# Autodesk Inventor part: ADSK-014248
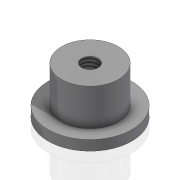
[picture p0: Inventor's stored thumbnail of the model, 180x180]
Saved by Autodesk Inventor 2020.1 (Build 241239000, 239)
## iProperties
Created: 2019-10
Part Number: ADSK-014248
Material: 1.0501 C35
Document SubType Name: Modeling
Designer: lutzd
Mass: 27.3113 g
Surface Area: 20.2779 cm^2
Volume: 3.48359 cm^3
Density: 7.84 g/cm^3
Appearance: Stahl
VLDS_Profile: Default Part
VLDS_TimeStamp: 2016-07-29
VLDS_FailCnt: 0
VLDS_AcceptCnt: 0
Dimensions: 25x25x14 mm
Mass: 0,027 kg
DocNumber: ADSK-014248
Folder: 01 - Themengebiete\Simplification\01 - Packaging machine\
VDS_Category: 3D Komponenten
VDS_NumSchm: Autodesk
Title: shaft
Author: lutzd
Revision Number: -
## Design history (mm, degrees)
sketch "Skizze1"
  geometry: C1 r 8.5 at (0, 0); 1 further point
  constraints: 1 centre point, 1 coincident
  dimensions: "d0" = 17 diameter of C1
extrude "Extrusion1" new body sketch "Skizze1" stored distance "d1" = 14; taper "d2" = 0 deg
sketch "Skizze2"
  geometry: C1 r 8.5 at (0, 0) reference; 2 further points
  constraints: 1 coincident
hole "Bohrung1" sketch "Skizze2" at (0, 0) diameter "d3" = 6.647; stored, may be unused: countersink angle "d7" = 90 deg, drill point angle "d9" = 118 deg; dims "d4" = 16, "d5" = 40, "d6" = 12, "d8" = 22.2
sketch "Skizze3"
  geometry: C1 r 12.5 at (0, 0); C2 r 3.324 at (0, 0) reference; C3 r 8.5 at (0, 0) reference; 1 further point
  constraints: 1 centre point, 1 coincident
  dimensions: "d10" = 25 diameter of C1
extrude "Extrusion2" join sketch "Skizze3" distance "d11" = 3; taper "d12" = 0 deg
node "Volumenkörper1"
